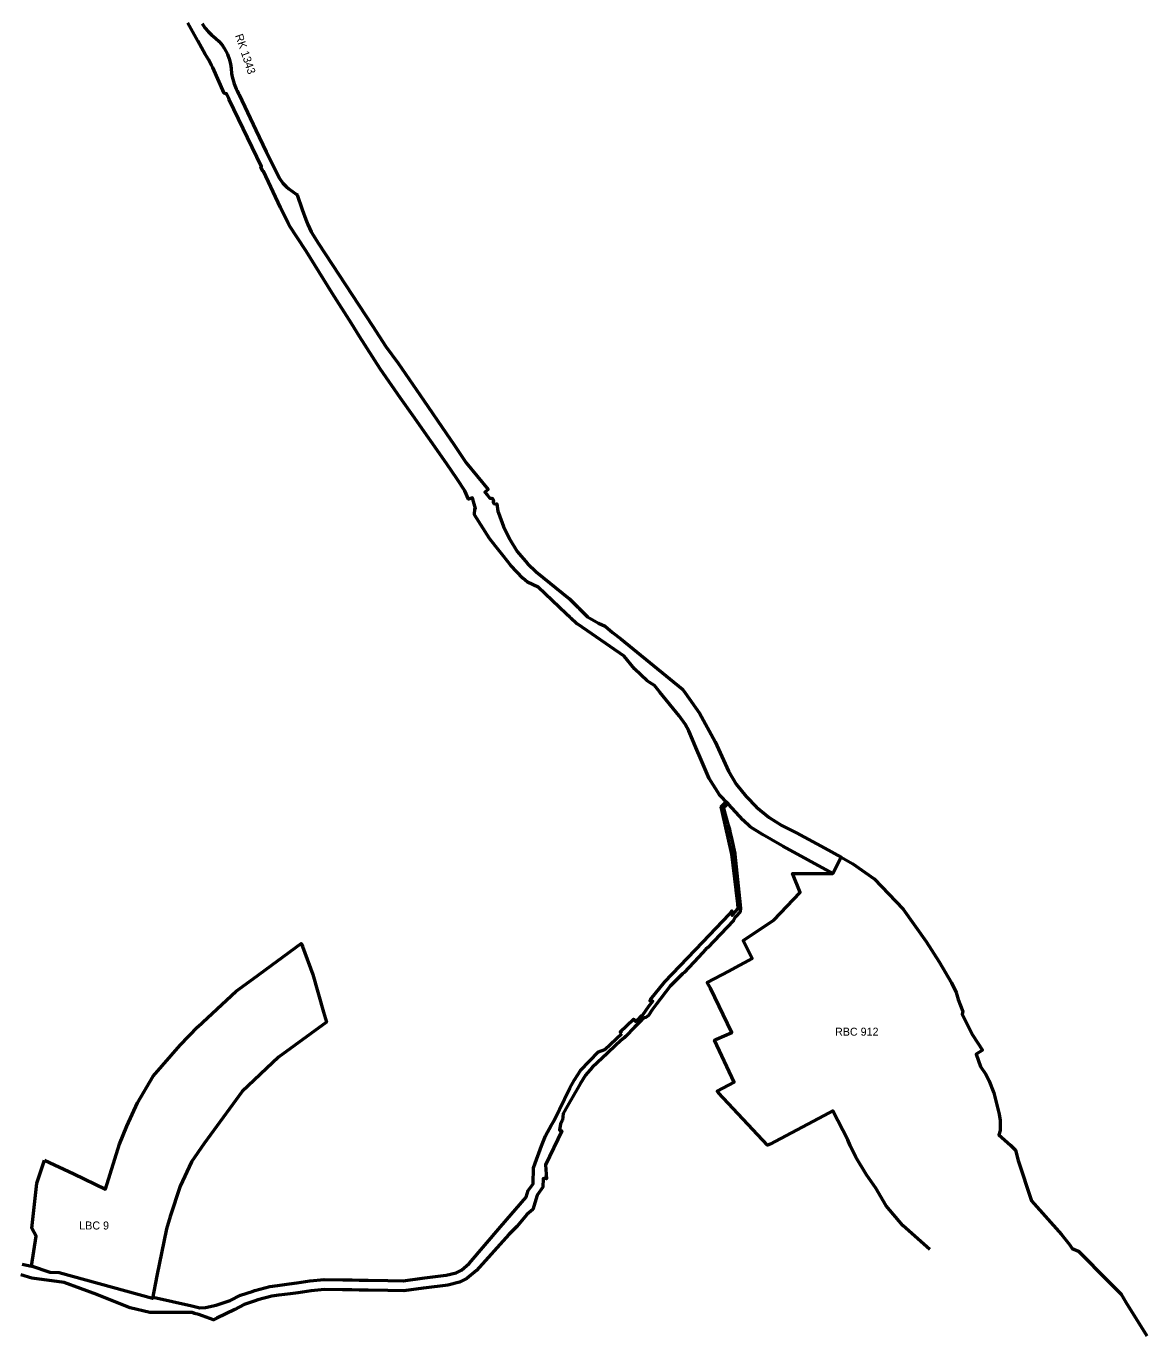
# Model space of a CAD drawing. Extents: x -650276 to -642570, y -1074314 to -1066553.
# Drawn here: x -647403 to -645724, y -1073097 to -1071134 of the extents above; entities that cross this region are included whole.
import ezdxf
from ezdxf.enums import TextEntityAlignment as Align

# ---------------------------------------------------------------- set-up
doc = ezdxf.new("R2010")
doc.units = 0
doc.header["$LTSCALE"] = 4.8
for name, color, linetype, lineweight in [('15', 7, 'Continuous', 53), ('19', 7, 'Continuous', 53), ('23', 7, 'Continuous', 53), ('27', 7, 'Continuous', 53)]:
    doc.layers.add(name, color=color, linetype=linetype, lineweight=lineweight)
doc.layers.add('63', color=7, linetype='Continuous')

msp = doc.modelspace()

# ---------------------------------------------------------------- linework, layer by layer
at = {"layer": '15'}
msp.add_lwpolyline([(-646048.986, -1072967.984), (-646089.39, -1072931.92), (-646114.5, -1072902.8), (-646129.91, -1072876.24), (-646143.99, -1072856.11), (-646159.73, -1072829.79), (-646168.17, -1072812.07), (-646171.72, -1072803.51), (-646194.287, -1072760.209), (-646199.72, -1072763.1), (-646288.27, -1072810.22), (-646292.17, -1072811.6), (-646365.52, -1072733.03), (-646367.72, -1072730.68), (-646342.08, -1072717.43), (-646371.66, -1072654.2), (-646368.51, -1072652.81), (-646345.75, -1072642.79), (-646377.84, -1072576.29), (-646380.47, -1072571.51), (-646382.41, -1072568.01), (-646350.18, -1072550.59), (-646340.16, -1072545.17), (-646320.62, -1072534.6), (-646315.32, -1072532.01), (-646328.45, -1072504.81), (-646282.47, -1072474.34), (-646243.17, -1072432.88), (-646254.75, -1072404.25), (-646194.19, -1072404.62), (-646181.907, -1072379.974), (-646164.02, -1072390), (-646132.34, -1072412.37), (-646088.86, -1072457.93), (-646054.33, -1072506.16), (-646034.83, -1072536.97), (-646016.46, -1072568.07), (-646009.27, -1072582.89), (-646006.21, -1072593.04), (-645999.14, -1072611.29), (-646000.45, -1072615.28), (-645984.88, -1072646.21), (-645969.97, -1072669.21), (-645979.44, -1072675.29), (-645972.67, -1072693.74), (-645965.19, -1072704.94), (-645960.61, -1072714.42), (-645953.06, -1072733.07), (-645944.81, -1072765.04), (-645943.38, -1072774.7), (-645943.65, -1072789.47), (-645945.37, -1072795.9), (-645927.96, -1072811.61), (-645920.56, -1072819.2), (-645916.48, -1072834.69), (-645896.61, -1072895.14), (-645851.64, -1072945.67), (-645839.57, -1072960.36), (-645835.46, -1072966.49), (-645825.96, -1072970.48), (-645781.57, -1073015.6), (-645761.93, -1073034.98), (-645754.82, -1073046.89), (-645723.602, -1073097.398)], dxfattribs=at)
at = {"layer": '19'}
for points in [[(-646394.24, -1072163.81), (-646370.83, -1072206.8), (-646350.46, -1072250.81), (-646339.07, -1072270.33), (-646324.17, -1072289.15), (-646308.74, -1072304.97), (-646289.9, -1072320.26), (-646270.62, -1072332.33), (-646248.46, -1072343.52), (-646206.07, -1072366.43), (-646181.907, -1072379.974), (-646194.19, -1072404.62), (-646269.41, -1072363.38), (-646273.54, -1072361), (-646299.75, -1072345.87), (-646318.09, -1072334.2), (-646328.57, -1072324.62), (-646351.15, -1072300), (-646364.12, -1072286.56), (-646379.86, -1072262.05), (-646391.77, -1072233.91), (-646399.6, -1072215.39), (-646404.67, -1072203.42), (-646410.14, -1072190.49), (-646415.84, -1072180.43), (-646424.56, -1072167.96), (-646453.42, -1072132.4), (-646461.56, -1072122.36), (-646469.41, -1072117.44), (-646472.72, -1072115.38), (-646491.69, -1072097.45), (-646507.28, -1072078.4), (-646576.63, -1072030.7), (-646578.46, -1072029.62), (-646586.85, -1072021.71), (-646587.71, -1072020.9), (-646588.12, -1072020.51), (-646593.88, -1072015.08), (-646636.01, -1071975.35), (-646651.94, -1071967.82), (-646659.02, -1071961.92), (-646676.92, -1071942.93), (-646688.02, -1071928.75), (-646699.77, -1071913.72), (-646708.81, -1071902.16), (-646731.16, -1071866.9), (-646730.82, -1071857.31), (-646730.1, -1071857.16), (-646733.03, -1071846.65), (-646734.49, -1071841.44), (-646740.35, -1071843.3), (-646746.05, -1071830.54), (-646757.15, -1071813.15), (-646773.23, -1071789.58), (-646823.68, -1071717.76), (-646842.09, -1071691.69), (-646872.61, -1071647.71), (-646903.67, -1071599.34), (-646916, -1071580.13), (-646944.58, -1071534.7), (-646983.8, -1071471.4), (-646997.05, -1071451.02), (-647008.5, -1071433.35), (-647010.73, -1071429.74), (-647021.47, -1071407.2), (-647022.03, -1071406.03), (-647047.61, -1071351.39), (-647048.59, -1071351.85), (-647051.77, -1071345.17), (-647050.89, -1071344.72), (-647098.97, -1071244.31), (-647099.74, -1071242.71), (-647102.06, -1071237.84), (-647102.72, -1071236.47), (-647102.97, -1071235.92), (-647103.31, -1071235.22), (-647104.17, -1071235.6), (-647106.7, -1071234.45), (-647123.7, -1071196.19), (-647125.44, -1071192.58), (-647130.1, -1071184.33), (-647135.21, -1071176.44), (-647146.28, -1071156.35), (-647161.13, -1071129.3)], [(-647139.72, -1071130.15), (-647135.45, -1071136.55), (-647130.77, -1071142.19), (-647125.39, -1071147.43), (-647119.65, -1071152.23), (-647114.14, -1071157.35), (-647109.3, -1071163.15), (-647106.48, -1071167.29), (-647103.94, -1071171.55), (-647101.72, -1071176.06), (-647098.97, -1071183.12), (-647097.18, -1071190.47), (-647096.16, -1071197.88), (-647095.44, -1071205.33), (-647094.61, -1071210.4), (-647091.74, -1071220.44), (-647088.5, -1071228.08), (-647087.93, -1071229.39), (-647087.3, -1071231.11), (-647085.13, -1071235.62), (-647084.13, -1071237.12), (-647059.06, -1071290.09), (-647043.61, -1071322.57), (-647040.39, -1071329.27), (-647024.36, -1071361.64), (-647018.53, -1071369.49), (-647013.75, -1071374.67), (-647009.87, -1071378.03), (-646998.54, -1071385.9), (-646997.58, -1071386.56), (-646996.97, -1071387.15), (-646989.58, -1071409.27), (-646984.18, -1071424.12), (-646981.06, -1071431.57), (-646976.09, -1071442.66), (-646965.35, -1071460.17), (-646884.4, -1071583.42), (-646864.39, -1071614.36), (-646845.66, -1071639.56), (-646807.19, -1071695.29), (-646773.79, -1071744.44), (-646761.95, -1071761.85), (-646743.9, -1071788.63), (-646710.82, -1071828.79), (-646715.81, -1071832.61), (-646712.47, -1071836.84), (-646708.56, -1071841.8), (-646706.02, -1071842.28), (-646705.52, -1071841.88), (-646702.75, -1071845), (-646703.44, -1071848.03), (-646702.16, -1071849.6), (-646698.84, -1071850.56), (-646697.91, -1071850.24), (-646696.3, -1071861.21), (-646695.43, -1071863.67), (-646688.11, -1071884.22), (-646678.98, -1071902.58), (-646667.19, -1071921.65), (-646652.07, -1071939.58), (-646638.81, -1071952.21), (-646588.96, -1071992.55), (-646575.92, -1072005.55), (-646575.57, -1072005.9), (-646574.48, -1072006.99), (-646565.98, -1072015.45), (-646565.01, -1072016.41), (-646561.99, -1072019.42), (-646545.56, -1072029.37), (-646535.68, -1072033.89), (-646524.34, -1072042.92), (-646512.21, -1072052.57), (-646419.55, -1072128.03), (-646415.61, -1072133.6), (-646394.24, -1072163.81)]]:
    msp.add_lwpolyline(points, dxfattribs=at)
at = {"layer": '23'}
msp.add_lwpolyline([(-647375.92, -1072833.99), (-647331.82, -1072854.49), (-647284.75, -1072877.79), (-647284.75, -1072877.79), (-647263.58, -1072809.97), (-647252.29, -1072783.24), (-647236.54, -1072748.09), (-647212.92, -1072708.05), (-647172.36, -1072661.69), (-647146.21, -1072634.02), (-647088.4, -1072580.868), (-647063.38, -1072562.42), (-646991.24, -1072509.24), (-646989.01, -1072513.62), (-646973.68, -1072555.68), (-646957.5, -1072612.09), (-646953.2, -1072627.45), (-647025.04, -1072679.96), (-647079.74, -1072731.1), (-647136.69, -1072808.98), (-647155.72, -1072836.46), (-647172.48, -1072872.92), (-647187.445, -1072918.804), (-647192.93, -1072936.82), (-647207.58, -1073007.44), (-647213.99, -1073041.45), (-647353.78, -1073003.1), (-647367.45, -1073002.47), (-647395.47, -1072993.25), (-647388.62, -1072948.03), (-647394.87, -1072936.08), (-647387.64, -1072868.69)], close=True, dxfattribs=at)
at = {"layer": '27'}
for points in [[(-646510.28, -1072644.42), (-646513.209, -1072641.935), (-646493.229, -1072622.74), (-646490.11, -1072626.15), (-646483.71, -1072620.35), (-646480.37, -1072617.18), (-646479.13, -1072616.26), (-646469.93, -1072603.28), (-646464.22, -1072595.84), (-646468.689, -1072595.119), (-646467.379, -1072593.42), (-646445.877, -1072566.771), (-646389.081, -1072507.297), (-646349.101, -1072465.372), (-646345.829, -1072460.475), (-646345.36, -1072467.29), (-646343.44, -1072465.25), (-646336.87, -1072457.3), (-646336.29, -1072457.22), (-646336.01, -1072456.23), (-646336.75, -1072450.07), (-646339.15, -1072430.13), (-646339.27, -1072429.13), (-646345.73, -1072375.51), (-646360.3, -1072310.87), (-646361.734, -1072304.631), (-646353.892, -1072297.158), (-646351.15, -1072300), (-646358.28, -1072306.16), (-646357.09, -1072310.35), (-646351.47, -1072330.27), (-646349.31, -1072337.93), (-646348.49, -1072341.51), (-646345.6, -1072354.14), (-646341, -1072374.27), (-646341.29, -1072375.31), (-646333.205, -1072451.289), (-646332.68, -1072456.19), (-646333.34, -1072461.67), (-646339.94, -1072469.58), (-646340.51, -1072469.67), (-646343.13, -1072475.03), (-646352.53, -1072484.78), (-646372.79, -1072505.81), (-646381.81, -1072515.17), (-646384.41, -1072517.86), (-646395.71, -1072529.8), (-646417.32, -1072552.64), (-646419.42, -1072554.86), (-646438.05, -1072573.49), (-646459.19, -1072600.85), (-646465.09, -1072608.61), (-646470.33, -1072617.33), (-646474.8, -1072620.09), (-646477.06, -1072620.67), (-646480.43, -1072623.86), (-646486.62, -1072629.97), (-646491.42, -1072634.69), (-646505.26, -1072648.68), (-646507.21, -1072650.52), (-646512.3, -1072655.3), (-646519.93, -1072662.47), (-646531.95, -1072673.77), (-646554.85, -1072695.37), (-646565.04, -1072706.87), (-646573.04, -1072719.85), (-646575.17, -1072723.31), (-646591.82, -1072752.54), (-646598.51, -1072764.27), (-646599.281, -1072774.132)], [(-647213.588, -1073039.315), (-647213.218, -1073039.42), (-647154.999, -1073052.287), (-647143.312, -1073055.421), (-647134.596, -1073054.974), (-647118.513, -1073051.327), (-647097.466, -1073044.268), (-647082.267, -1073036.684), (-647064.784, -1073030.747), (-647060.677, -1073029.351), (-647037.971, -1073023.24), (-647026.763, -1073021.811), (-647009.402, -1073019.582), (-646997.824, -1073018.092), (-646978.077, -1073014.931), (-646956.919, -1073012.775), (-646928.807, -1073013.313), (-646914.796, -1073013.573), (-646904.131, -1073013.793), (-646890.523, -1073014.073), (-646861.07, -1073014.672), (-646838.25, -1073014.938), (-646809.778, -1073011.019), (-646773.9, -1073006.461), (-646758.883, -1073002.885), (-646751.061, -1072999.106), (-646739.241, -1072988.798), (-646692.432, -1072934.135), (-646653.846, -1072889.44), (-646650.798, -1072879.828), (-646643.574, -1072869.57), (-646642.939, -1072845.68), (-646640.313, -1072838.394), (-646631.08, -1072812.68), (-646624.81, -1072797.42), (-646616.6, -1072782.31), (-646612.11, -1072774.56), (-646588.659, -1072726.214), (-646581.578, -1072713.897), (-646572.611, -1072699.551), (-646545.372, -1072671.533), (-646535.97, -1072668.39), (-646510.28, -1072644.42)], [(-646599.281, -1072774.132), (-646602.497, -1072779.637), (-646603.99, -1072788.9), (-646600.37, -1072790.04), (-646625.02, -1072841.21), (-646623.25, -1072862.05), (-646623.95, -1072857.6), (-646623.67, -1072862.03), (-646628.36, -1072861.71), (-646628.7, -1072874.5), (-646637.2, -1072886.57), (-646644.06, -1072908.21), (-646652.76, -1072915.66), (-646668.09, -1072933.43), (-646680.07, -1072945.74), (-646728.558, -1072999.384), (-646742.721, -1073011.735), (-646753.824, -1073017.1), (-646771.21, -1073021.24), (-646807.81, -1073025.89), (-646837.31, -1073029.95), (-646861.31, -1073029.67), (-646890.83, -1073029.07), (-646904.44, -1073028.79), (-646915.09, -1073028.57), (-646929.09, -1073028.31), (-646956.3, -1073027.79), (-646976.13, -1073029.81), (-646995.68, -1073032.94), (-647007.49, -1073034.46), (-647024.86, -1073036.69), (-647035.06, -1073037.99), (-647056.31, -1073043.71), (-647059.96, -1073044.95), (-647076.48, -1073050.56), (-647090.83, -1073057.72), (-647117.73, -1073070.84), (-647122.68, -1073073.23), (-647144.47, -1073065.23), (-647150.95, -1073063.78), (-647154.77, -1073062.68), (-647218.06, -1073062.37), (-647247.46, -1073055.63), (-647263.8, -1073049), (-647297.53, -1073035.3), (-647346.22, -1073017.52), (-647394.782, -1073011.002), (-647411.34, -1073005.89)], [(-647409.484, -1072990.206), (-647395.47, -1072993.25), (-647395.47, -1072993.25)]]:
    msp.add_lwpolyline(points, dxfattribs=at)

# ---------------------------------------------------------------- texts
at = {"layer": '63'}
msp.add_text('RK 1343', height=12, rotation=288.63, dxfattribs=at).set_placement((-647080.392, -1071177.786), align=Align.CENTER)
for s, p in [('RBC 912', (-646158.336, -1072647.538)), ('LBC 9', (-647301.531, -1072938.022))]:
    msp.add_text(s, height=12, dxfattribs=at).set_placement(p, align=Align.CENTER)

doc.saveas('drawing.dxf')
